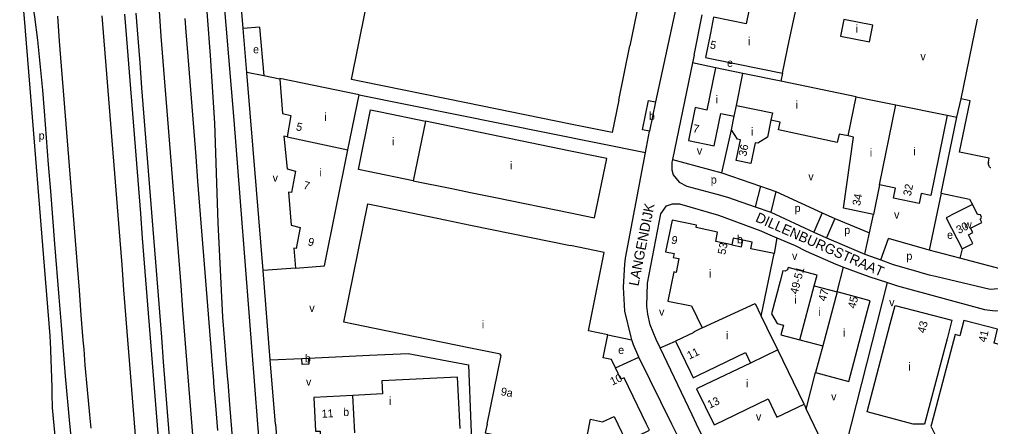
# Model space of a CAD drawing. Extents: x 157699 to 159683, y 381451 to 383293.
# Drawn here: x 157774.5 to 158260, y 381748.7 to 381952.4 of the extents above; entities that cross this region are included whole.
import ezdxf

# ---------------------------------------------------------------- set-up
doc = ezdxf.new("R2010")
doc.units = 0
for name, color, linetype in [('BLT_Basislijn', 7, 'Continuous'), ('BLT_Bebouwing', 7, 'Continuous'), ('BLT_Centroide', 7, 'Continuous'), ('BLT_Gemeentegrens', 7, 'Continuous'), ('BLT_Huisnummer', 7, 'Continuous'), ('BLT_Huisnummer_reeks', 7, 'Continuous'), ('BLT_Onderverdeling_panden', 7, 'Continuous'), ('BLT_Straatnaam', 7, 'Continuous')]:
    doc.layers.add(name, color=color, linetype=linetype)

msp = doc.modelspace()

# ---------------------------------------------------------------- linework, layer by layer
at = {"layer": 'BLT_Basislijn'}
for p, q in [((158108.6, 381985.35), (158092.48, 381911.08)), ((157886.35, 381947.73), (157885.68, 381956.04)), ((157894.49, 381948.53), (157886.35, 381947.73)), ((157888.13, 381925.82), (157886.35, 381947.73)), ((158111.75, 381934.53), (158110.95, 381930.65)), ((158122.49, 381928.06), (158110.95, 381930.65)), ((157896.62, 381924.1), (157888.13, 381925.82)), ((157904.71, 381922.46), (157896.62, 381924.1)), ((158155.92, 381925.46), (158155.09, 381921.39)), ((157944.3, 381914.71), (158087.44, 381885.73)), ((158243.06, 381903.54), (158245.23, 381912.56)), ((158235.22, 381865.43), (158243.06, 381903.54)), ((158238.32, 381904.43), (158243.06, 381903.54)), ((158125.63, 381875.63), (158130.42, 381897.19)), ((158100.97, 381882.28), (158125.63, 381875.63)), ((158125.63, 381875.63), (158144.93, 381868.9)), ((158144.93, 381868.9), (158142.31, 381858.66)), ((158144.93, 381868.9), (158152.68, 381866.26)), ((158152.68, 381866.26), (158150.05, 381856.02)), ((158152.68, 381866.26), (158175.84, 381855.6)), ((158235.22, 381865.43), (158229.35, 381836.9)), ((158175.84, 381855.6), (158171.66, 381845.94)), ((158175.84, 381855.6), (158182.1, 381852.72)), ((158199.43, 381845.56), (158201.4, 381854.83)), ((158182.1, 381852.72), (158177.91, 381843.04)), ((158182.1, 381852.72), (158199.43, 381845.56)), ((158148.45, 381845.12), (158153.15, 381843.11)), ((158197.19, 381835.02), (158199.43, 381845.56)), ((158153.15, 381843.11), (158151.74, 381835.3)), ((158205.07, 381832.07), (158208.87, 381842.72)), ((158229.35, 381836.9), (158208.87, 381842.72)), ((158244.53, 381832.89), (158229.35, 381836.9)), ((158245.77, 381837.57), (158244.53, 381832.89)), ((158270.37, 381826.06), (158244.53, 381832.89)), ((157912.47, 381828), (157896.31, 381826.71)), ((158183.28, 381816.07), (158186.45, 381828.48)), ((158222.46, 381826.59), (158226.2, 381825.53)), ((158190.41, 381750), (158208.47, 381820.72)), ((158068.69, 381794.63), (158080.69, 381792.18)), ((158094.88, 381788.04), (158102.51, 381791.51)), ((158150.96, 381792.3), (158153.63, 381787.09)), ((157902.49, 381750), (157899.91, 381782.03)), ((158072.48, 381778.07), (158084.17, 381783.51)), ((158167.81, 381757.42), (158172.49, 381775.75)), ((158166.78, 381760.01), (158167.81, 381757.42)), ((158167.81, 381757.42), (158183.84, 381724.24)), ((157902.49, 381750), (157905.84, 381708.55)), ((158000.2, 381750), (158001.76, 381713.17)), ((158103.23, 381744.54), (158100.56, 381750)), ((158183.84, 381724.24), (158190.41, 381750))]:
    msp.add_line(p, q, dxfattribs=at)
for points in [[(157890.71, 381788.57), (157881.79, 381901.93), (157865.93, 382092.23)], [(157777.17, 381985.59), (157779.91, 381967.9), (157782.03, 381953.71), (157783.5, 381941.99), (157784.77, 381930.34), (157786.03, 381916.92), (157786.85, 381906.41), (157787.93, 381893.2), (157788.96, 381879.81), (157790.06, 381866.4), (157792.11, 381840.1), (157794.2, 381813.47), (157795.32, 381799.46), (157797.34, 381773.96), (157799.47, 381750.35), (157800.68, 381738.99), (157802.74, 381724.81), (157806.1, 381703.5), (157809.24, 381684.74), (157813.48, 381660.81)], [(157876.25, 381803.45), (157873.92, 381850.56), (157872.28, 381900.4), (157870.06, 381934.31), (157867.05, 381973.8)], [(157844, 381743.22), (157843.01, 381755.68), (157842.03, 381768.14), (157841.04, 381780.6), (157840.06, 381793.07), (157839.07, 381805.53), (157838.09, 381817.99), (157837.1, 381830.45), (157836.11, 381842.91), (157835.13, 381855.37), (157834.14, 381867.83), (157833.16, 381880.29), (157832.17, 381892.75), (157831.19, 381905.22), (157830.2, 381917.68), (157829.22, 381930.14), (157828.23, 381942.6), (157827.25, 381955.06)], [(157849.58, 381743.66), (157848.59, 381756.12), (157847.61, 381768.59), (157846.62, 381781.05), (157845.64, 381793.51), (157844.65, 381805.97), (157843.67, 381818.43), (157842.68, 381830.89), (157841.7, 381843.35), (157840.71, 381855.81), (157839.73, 381868.27), (157838.74, 381880.74), (157837.76, 381893.2), (157836.77, 381905.66), (157835.79, 381918.12), (157834.8, 381930.58), (157833.81, 381943.04), (157832.83, 381955.5)], [(157844.29, 381956.41), (157845.28, 381943.95), (157846.26, 381931.49), (157847.25, 381919.02), (157848.23, 381906.56), (157849.22, 381894.1), (157850.21, 381881.64), (157851.19, 381869.18), (157852.18, 381856.72), (157853.16, 381844.26), (157854.15, 381831.8), (157855.13, 381819.34), (157856.12, 381806.87), (157857.1, 381794.41), (157858.09, 381781.95), (157859.07, 381769.49), (157860.06, 381757.03), (157861.04, 381744.57)], [(157793.48, 381953.94), (157794.46, 381941.48), (157795.45, 381929.02), (157796.44, 381916.56), (157797.42, 381904.1), (157798.41, 381891.64), (157799.39, 381879.18), (157800.38, 381866.71), (157801.36, 381854.25), (157802.35, 381841.79), (157803.33, 381829.33), (157804.32, 381816.87), (157805.3, 381804.41), (157806.29, 381791.95), (157806.65, 381787.38), (157807.29, 381779.49), (157808.36, 381767.04), (157809.51, 381754.59), (157809.83, 381751.35), (157810.17, 381747.87)], [(157815.78, 381954.15), (157816.77, 381941.69), (157817.75, 381929.23), (157818.74, 381916.77), (157819.72, 381904.31), (157820.71, 381891.85), (157821.69, 381879.39), (157822.68, 381866.93), (157823.67, 381854.46), (157824.65, 381842), (157825.64, 381829.54), (157826.62, 381817.08), (157827.61, 381804.62), (157828.59, 381792.16), (157829.58, 381779.7), (157830.56, 381767.24), (157831.55, 381754.78), (157832.53, 381742.31)], [(157857.16, 381952.88), (157857.69, 381946.19), (157858.68, 381933.73), (157859.66, 381921.26), (157860.65, 381908.8), (157861.63, 381896.34), (157862.62, 381883.88), (157863.6, 381871.42), (157864.59, 381858.96), (157865.57, 381846.5), (157866.56, 381834.04), (157867.54, 381821.58), (157868.53, 381809.11), (157869.51, 381796.65), (157870.5, 381784.19), (157870.72, 381781.46), (157871.49, 381771.73), (157871.58, 381770.48), (157872.47, 381759.27), (157873.47, 381746.81)], [(158111.75, 381934.53), (158115.79, 381954.57)], [(157894.49, 381948.53), (157896.62, 381924.1)], [(158110.95, 381930.65), (158100.97, 381882.28)], [(157896.31, 381826.71), (157893.03, 381867.34), (157888.13, 381925.82)], [(158087.44, 381885.73), (158089.47, 381896.42)], [(158080.69, 381792.18), (158080.28, 381793.44), (158077.14, 381806.43), (158076.42, 381818.53), (158077.07, 381829.89), (158077.45, 381832.91), (158087.44, 381885.73)], [(158100.97, 381882.28), (158100.68, 381880.89), (158100.65, 381877.19), (158101.32, 381874.69), (158104.26, 381871.03), (158108.08, 381869), (158123.21, 381864.92)], [(158123.21, 381864.92), (158128.46, 381863.51), (158142.31, 381858.66)], [(158235.22, 381865.43), (158249.48, 381862.49), (158250.92, 381859.85)], [(158094.88, 381788.04), (158092.82, 381792.36), (158089.86, 381799.53), (158088.7, 381804.98), (158088.19, 381809.03), (158088.46, 381820.4), (158095.11, 381855.12), (158097.98, 381859.1), (158100.91, 381860.2), (158104.5, 381860.05), (158124.01, 381854.48), (158145.13, 381846.54), (158148.45, 381845.12)], [(158142.31, 381858.66), (158150.05, 381856.02)], [(158150.05, 381856.02), (158171.66, 381845.94)], [(158171.66, 381845.94), (158177.91, 381843.04)], [(158153.15, 381843.11), (158162.25, 381839.21), (158167.78, 381836.4), (158182.62, 381829.89), (158186.45, 381828.48)], [(158177.91, 381843.04), (158197.19, 381835.02)], [(158197.19, 381835.02), (158205.07, 381832.07)], [(158205.07, 381832.07), (158211.26, 381829.76), (158222.46, 381826.59)], [(157899.91, 381782.03), (157896.31, 381826.71)], [(158186.45, 381828.48), (158199.15, 381823.83), (158208.47, 381820.72)], [(158226.2, 381825.53), (158229.33, 381824.65), (158232.39, 381823.92)], [(158232.39, 381823.92), (158259.72, 381817.41), (158265.79, 381817.9)], [(158208.47, 381820.72), (158213.48, 381819.05), (158257.01, 381807.31), (158262.26, 381806.59), (158268.02, 381807.18)], [(157886.27, 381679.89), (157885.83, 381685.13), (157884.78, 381697.58), (157883.75, 381710.03), (157883.43, 381713.91), (157882.72, 381722.48), (157881.71, 381734.94), (157880.7, 381747.39), (157879.7, 381759.85), (157878.81, 381771.05), (157878.71, 381772.3), (157877.94, 381782.04), (157877.73, 381784.76), (157876.74, 381797.22), (157876.25, 381803.45)], [(158084.17, 381783.51), (158081.55, 381789.55), (158080.69, 381792.18)], [(157893.74, 381750), (157890.71, 381788.57)], [(157949.51, 381784.42), (157968.84, 381785.35), (157998.95, 381779.64), (158000.2, 381750)], [(158113.04, 381750), (158110.81, 381754.62), (158094.88, 381788.04)], [(157899.91, 381782.03), (157915.76, 381782.73)], [(157919.06, 381782.91), (157949.51, 381784.42)], [(158100.56, 381750), (158084.17, 381783.51)], [(157899.14, 381681.43), (157893.74, 381750)], [(158135.8, 381701.79), (158135.43, 381702.75), (158124.84, 381725.53), (158113.04, 381750)]]:
    msp.add_lwpolyline(points, dxfattribs=at)
at = {"layer": 'BLT_Bebouwing'}
for p, q in [((158245.23, 381912.56), (158253.39, 381952.43)), ((158074.09, 381912), (158079.65, 381939.18)), ((157904.71, 381922.46), (157905.97, 381905.27)), ((158155.09, 381921.39), (158136.16, 381925.23)), ((158192.83, 381913.72), (158155.09, 381921.39)), ((158192.83, 381913.72), (158200.95, 381912.05)), ((158200.95, 381912.05), (158212.68, 381909.65)), ((158092.48, 381911.08), (158089.47, 381896.42)), ((158130.42, 381897.19), (158131.81, 381903.96)), ((158258.81, 381880.4), (158258.84, 381880.62)), ((158258.83, 381880.16), (158258.84, 381879.94)), ((158258.87, 381880.89), (158258.87, 381880.86)), ((158258.89, 381879.73), (158258.95, 381879.49)), ((158259.03, 381879.3), (158259.13, 381879.08)), ((158259.38, 381878.7), (158259.25, 381878.89)), ((158259.69, 381878.37), (158259.55, 381878.52)), ((158260.06, 381878.1), (158259.9, 381878.21)), ((158171.84, 381819.14), (158183.28, 381816.07)), ((158145.32, 381803.99), (158150.96, 381792.3)), ((158164.63, 381792.13), (158176.05, 381789.09)), ((158166.78, 381760.01), (158153.63, 381787.09)), ((158176.05, 381789.09), (158172.49, 381775.75)), ((157915.76, 381782.73), (157919.06, 381782.91))]:
    msp.add_line(p, q, dxfattribs=at)
for points in [[(158094.36, 382010.89), (158092.13, 381999.99), (158079.65, 381939.18)], [(158155.92, 381925.46), (158159.22, 381941.61), (158162.78, 381957.8), (158140.23, 381962.43), (158137.74, 381950.1), (158121.53, 381953.4)], [(157997.87, 381910.61), (157945.37, 381921.28), (157940.47, 381922.28), (157947.41, 381956.21)], [(158121.53, 381953.4), (158119.92, 381945.56), (158117.43, 381933.3)], [(158117.43, 381933.3), (158122.3, 381932.31), (158155.92, 381925.46)], [(158122.49, 381928.06), (158118.15, 381907.05), (158112.31, 381908.26), (158108.95, 381891.76), (158121.86, 381889.09), (158125.13, 381905.33), (158131.81, 381903.96)], [(158136.16, 381925.23), (158122.49, 381928.06)], [(157944.3, 381914.71), (157904.68, 381922.79), (157904.71, 381922.46)], [(157938.72, 381887.13), (157944.3, 381914.71)], [(158074.09, 381912), (158070.77, 381895.78), (158065.87, 381896.78), (158050, 381900.01)], [(158089.47, 381896.42), (158085.94, 381897.16), (158088.93, 381911.8), (158092.48, 381911.08)], [(158244.48, 381886.01), (158249.76, 381911.63), (158245.23, 381912.56)], [(157971.35, 381871.66), (157948.88, 381876.24), (157943.98, 381877.23), (157950.08, 381907.12)], [(157950.08, 381907.12), (157954.98, 381906.1), (157977.49, 381901.47)], [(158050, 381900.01), (157997.87, 381910.61)], [(158212.68, 381909.65), (158238.32, 381904.43)], [(157905.97, 381905.27), (157910.23, 381904.3), (157908.29, 381893.7)], [(158150.14, 381902), (158148.4, 381893.51), (158143.67, 381890.4), (158142.28, 381890.68), (158140.15, 381880.35), (158132.78, 381881.82), (158134.9, 381892.19), (158133.54, 381892.47), (158130.42, 381897.19)], [(158188.76, 381894.06), (158184.22, 381894.99), (158183.29, 381890.82), (158153.93, 381897.07), (158154.76, 381901.05), (158150.14, 381902)], [(158238.32, 381904.43), (158230.08, 381864.32)], [(157995.22, 381897.81), (157977.49, 381901.47)], [(158050, 381886.53), (158000, 381896.83), (157995.22, 381897.81)], [(157908.29, 381893.7), (157906.65, 381894), (157908.29, 381877.59), (157912.55, 381876.42), (157910.54, 381865.72), (157908.98, 381866), (157910.42, 381849.51), (157914.87, 381848.35), (157912.86, 381837.78), (157911.66, 381838.03), (157912.47, 381828)], [(158186.49, 381857.9), (158191.47, 381893.5), (158188.76, 381894.06)], [(157912.47, 381828), (157926.98, 381829.15), (157938.72, 381887.13)], [(158062.03, 381853.14), (158068.09, 381882.8), (158063.2, 381883.81), (158050, 381886.53)], [(158258.87, 381880.89), (158259.27, 381882.93), (158244.48, 381886.01)], [(158258.81, 381880.4), (158258.81, 381880.37), (158258.83, 381880.16)], [(158258.87, 381880.86), (158258.86, 381880.82), (158258.84, 381880.62)], [(158258.84, 381879.94), (158258.84, 381879.91), (158258.89, 381879.73)], [(158258.95, 381879.49), (158258.96, 381879.47), (158259.03, 381879.3)], [(158259.13, 381879.08), (158259.14, 381879.05), (158259.25, 381878.89)], [(158259.38, 381878.7), (158259.4, 381878.67), (158259.55, 381878.52)], [(158259.69, 381878.37), (158259.72, 381878.34), (158259.9, 381878.21)], [(157971.35, 381871.66), (157990.64, 381867.72)], [(157990.64, 381867.72), (158000, 381865.82), (158012.43, 381863.28), (158050, 381855.6)], [(158204.46, 381869.62), (158201.4, 381854.83)], [(158230.08, 381864.32), (158225.32, 381865.25), (158224.3, 381860.33), (158211.44, 381862.98), (158212.49, 381867.94), (158204.46, 381869.62)], [(157952.02, 381797.81), (157941.53, 381799.96), (157936.63, 381800.97), (157948.76, 381860.05)], [(157948.76, 381860.05), (157953.66, 381859.05), (157987.34, 381852.12)], [(158201.4, 381854.83), (158186.49, 381857.9)], [(158250.92, 381859.85), (158242.24, 381855.41), (158237.79, 381853.14)], [(158254.85, 381854.57), (158253.98, 381854.85), (158253.58, 381854.66), (158250.92, 381859.85)], [(158050, 381855.6), (158057.13, 381854.14), (158062.03, 381853.14)], [(158237.79, 381853.14), (158245.77, 381837.57)], [(158245.77, 381837.57), (158251.12, 381840.29), (158248.9, 381844.65), (158251.05, 381845.76), (158249.98, 381847.89), (158255.58, 381850.77), (158254.75, 381852.42), (158255.11, 381852.61), (158255.42, 381853.45), (158254.85, 381854.57)], [(157987.34, 381852.12), (158000, 381849.52), (158050, 381839.24)], [(158122.56, 381841.33), (158123.53, 381845.99), (158112.74, 381848.24), (158112.98, 381849.41), (158100.73, 381851.91), (158097.52, 381836.19), (158101.78, 381835.27), (158101.36, 381833.35), (158104.16, 381832.77), (158103.45, 381829.29)], [(158066.87, 381835.78), (158061.97, 381836.78), (158050, 381839.24)], [(158130.58, 381839.66), (158122.56, 381841.33)], [(158136.07, 381841.99), (158131.28, 381843.01), (158130.58, 381839.66)], [(158151.74, 381835.3), (158140.18, 381837.65), (158140.86, 381840.99), (158136.07, 381841.99)], [(158068.69, 381794.63), (158058.9, 381796.63), (158066.87, 381835.78)], [(158145.32, 381803.99), (158151.74, 381835.3)], [(158103.45, 381829.29), (158102.73, 381825.81), (158101.58, 381826.07), (158098.58, 381811.45), (158110.47, 381809.1), (158115.76, 381798.07)], [(158171.84, 381819.14), (158173.21, 381824.38), (158158.78, 381828.24), (158158.47, 381827.11), (158157.27, 381826.41), (158156.16, 381826.7), (158154.76, 381821.38), (158150.48, 381805.12), (158153.24, 381800.36), (158156.47, 381799.49), (158155.18, 381794.65), (158164.63, 381792.13)], [(158172.49, 381775.75), (158189.1, 381771.32), (158198.5, 381806.81), (158199.78, 381811.64), (158183.28, 381816.07)], [(158221.26, 381750), (158198.23, 381756.02), (158209.83, 381800.12), (158212.27, 381809.36), (158240.64, 381801.91), (158238.19, 381792.67)], [(158269.81, 381750), (158268.43, 381752.77), (158277.65, 381786.21), (158261.76, 381790.51), (158263.5, 381797.38), (158246.68, 381801.84), (158244.64, 381794.18), (158242.34, 381794.76), (158230.44, 381750)], [(158008.27, 381750), (158015.25, 381784.25), (158014.93, 381784.33), (158015.07, 381784.87), (158000, 381787.96), (157952.02, 381797.81)], [(158115.76, 381798.07), (158111.47, 381796), (158111.62, 381795.7), (158102.51, 381791.51)], [(158072.48, 381778.07), (158070.44, 381782.29), (158066.33, 381783.12), (158068.69, 381794.63)], [(158102.51, 381791.51), (158110.02, 381775.93), (158111.37, 381773.15), (158114.03, 381774.44), (158118.53, 381776.62), (158137.5, 381785.79), (158139.92, 381780.51)], [(158238.19, 381792.67), (158226.95, 381750)], [(157919.06, 381782.91), (157919.19, 381779.91), (157915.9, 381779.73), (157915.76, 381782.73)], [(158139.92, 381780.51), (158117.55, 381769.76), (158113.05, 381767.6), (158121.58, 381750)], [(158088.01, 381750), (158076.86, 381773.19), (158075.21, 381772.43), (158072.48, 381778.07)], [(157994.79, 381747.81), (157993.51, 381773.49), (157955.6, 381771.62), (157955.93, 381765.08), (157941.1, 381764.32)], [(157941.1, 381764.32), (157921.69, 381763.33), (157922.56, 381746.39), (157924.78, 381746.5), (157924.85, 381744.83)], [(158122.57, 381750), (158127.08, 381752.16), (158148.72, 381762.55), (158153.14, 381753.46), (158166.78, 381760.01)], [(158050, 381736.86), (158051.69, 381736.51), (158056.59, 381735.5), (158060.04, 381752.38)], [(158060.04, 381752.38), (158066.03, 381751.1), (158071.79, 381753.82), (158073.63, 381750)], [(158008.27, 381750), (158007.37, 381745.62), (158050, 381736.86)], [(158073.63, 381750), (158077.8, 381741.31), (158089.49, 381746.92)], [(158089.49, 381746.92), (158088.01, 381750)], [(158121.58, 381750), (158121.77, 381749.61), (158122.57, 381750)], [(158226.95, 381750), (158221.26, 381750)], [(158230.44, 381750), (158230.14, 381748.88), (158248.59, 381711.93)]]:
    msp.add_lwpolyline(points, dxfattribs=at)
msp.add_lwpolyline([(158186.6, 381952.28), (158184.99, 381944.01), (158199.44, 381941.2), (158201.04, 381949.48)], close=True, dxfattribs=at)
at = {"layer": 'BLT_Gemeentegrens'}
msp.add_lwpolyline([(157821.62, 381457.57), (157813.89, 381461.78), (157813.54, 381462.57), (157812.82, 381466.24), (157811.88, 381479.42), (157808.82, 381528.32), (157802.33, 381638.43), (157799.33, 381669.9), (157791.09, 381758.11), (157790.95, 381765.11), (157790.89, 381768.47), (157790.24, 381786.83), (157790.21, 381787.45), (157789.89, 381794.11), (157787.02, 381829.01), (157779.86, 381917.92), (157776.96, 381954.82), (157774.91, 381971.23), (157774.54, 381972.47), (157774.93, 381972.56), (157774.52, 381975.12)], dxfattribs=at)
at = {"layer": 'BLT_Onderverdeling_panden'}
for p, q in [((158132.88, 381909.23), (158136.16, 381925.23)), ((158131.81, 381903.96), (158132.88, 381909.23)), ((158204.46, 381869.62), (158212.68, 381909.65)), ((157977.49, 381901.47), (157971.35, 381871.66)), ((157908.29, 381893.7), (157938.72, 381887.13)), ((158164.63, 381792.13), (158171.84, 381819.14)), ((158183.28, 381816.07), (158176.05, 381789.09)), ((158153.63, 381787.09), (158139.92, 381780.51)), ((157942.11, 381745.57), (157941.1, 381764.32))]:
    msp.add_line(p, q, dxfattribs=at)
for points in [[(158188.76, 381894.06), (158192.83, 381913.72)], [(158132.88, 381909.23), (158150.88, 381905.6), (158150.14, 381902)], [(158130.58, 381839.66), (158135.38, 381838.66), (158136.07, 381841.99)], [(158115.76, 381798.07), (158142.28, 381810.29), (158145.32, 381803.99)]]:
    msp.add_lwpolyline(points, dxfattribs=at)

# ---------------------------------------------------------------- texts
at = {"layer": 'BLT_Centroide'}
for s, p in [('i', (158192.52, 381945.69)), ('i', (158138.73, 381939.44)), ('e', (157891.31, 381935.42)), ('e', (158128.23, 381928.61)), ('v', (158224.9, 381931.92)), ('i', (158122.56, 381910.31)), ('i', (158162.48, 381907.66)), ('i', (157926.95, 381901.6)), ('b', (158089.2, 381902.11)), ('i', (158140.25, 381894.28)), ('p', (157784.15, 381892.26)), ('i', (157960.73, 381889.36)), ('v', (158113.16, 381884.73)), ('i', (158199.59, 381883.77)), ('i', (158221.39, 381884.41)), ('i', (157924.5, 381873.86)), ('i', (158019.74, 381877.31)), ('v', (157901.11, 381871.21)), ('p', (158120.11, 381870.23)), ('v', (158168.86, 381871.87)), ('p', (158162.03, 381856.04)), ('v', (158211.73, 381852.77)), ('w', (158246.69, 381847.86)), ('b', (158133.17, 381840.41)), ('p', (158186.81, 381845.03)), ('e', (158238.21, 381842.61)), ('v', (158160.71, 381832.07)), ('p', (158217.9, 381832.07)), ('i', (158119.19, 381823.25)), ('i', (158161.84, 381810.16)), ('v', (158209.29, 381808.89)), ('v', (157919.44, 381806.05)), ('v', (158094.25, 381804.15)), ('i', (158173.95, 381804.11)), ('i', (158005.66, 381797.78)), ('i', (158127.64, 381792.38)), ('i', (158186.14, 381793.72)), ('e', (158073.82, 381785.05)), ('b', (157917.19, 381780.81)), ('i', (158218.84, 381776.77)), ('v', (157917.76, 381769.18)), ('i', (158137.71, 381768.34)), ('i', (157959.22, 381759.56)), ('v', (158180.27, 381761.8)), ('b', (157936.34, 381754.04)), ('v', (158142.69, 381751.75))]:
    msp.add_text(s, height=4, dxfattribs=at).set_placement(p)
at = {"layer": 'BLT_Huisnummer'}
for s, rotation, p in [('5', 348.4933, (158119.48, 381937.9)), ('5', 347.1952, (157912.56, 381897.01)), ('7', 349.1322, (158110.96, 381896.02)), ('36', 78.3763, (158137.82, 381883.64)), ('32', 78.3822, (158220.09, 381863.81)), ('34', 78.4308, (158194.7, 381858.9)), ('30', 26.9875, (158244.04, 381844.99)), ('47', 74.9897, (158177.55, 381811.11)), ('45', 75.1761, (158192.34, 381807.49)), ('43', 75.1758, (158227.13, 381795.18)), ('41', 77.0403, (158257.68, 381790.61)), ('11', 25.7914, (158109.4, 381782.21)), ('13', 25.6476, (158119.58, 381757.66)), ('11', 2.7481, (157925.65, 381753.13))]:
    msp.add_text(s, height=4, rotation=rotation, dxfattribs=at).set_placement(p)
at = {"layer": 'BLT_Huisnummer_reeks'}
for s, rotation, p in [('7', 344.7392, (157916.17, 381867.75)), ('9', 348.4608, (158100.11, 381840.34)), ('9', 345.3718, (157918.39, 381839.51)), ('53', 78.4328, (158127.37, 381834.49)), ('49-51', 75.0568, (158163.46, 381814.69)), ('10', 24.9212, (158070.9, 381769.22)), ('9a', 349.9212, (158014.91, 381764.46))]:
    msp.add_text(s, height=4, rotation=rotation, dxfattribs=at).set_placement(p)
at = {"layer": 'BLT_Straatnaam'}
for s, rotation, p in [('LANGENDIJK', 78.8091, (158083.9, 381818.71)), ('DILLENBURGSTRAAT', 336.2133, (158142.05, 381851.48))]:
    msp.add_text(s, height=5, rotation=rotation, dxfattribs=at).set_placement(p)

doc.saveas('drawing.dxf')
